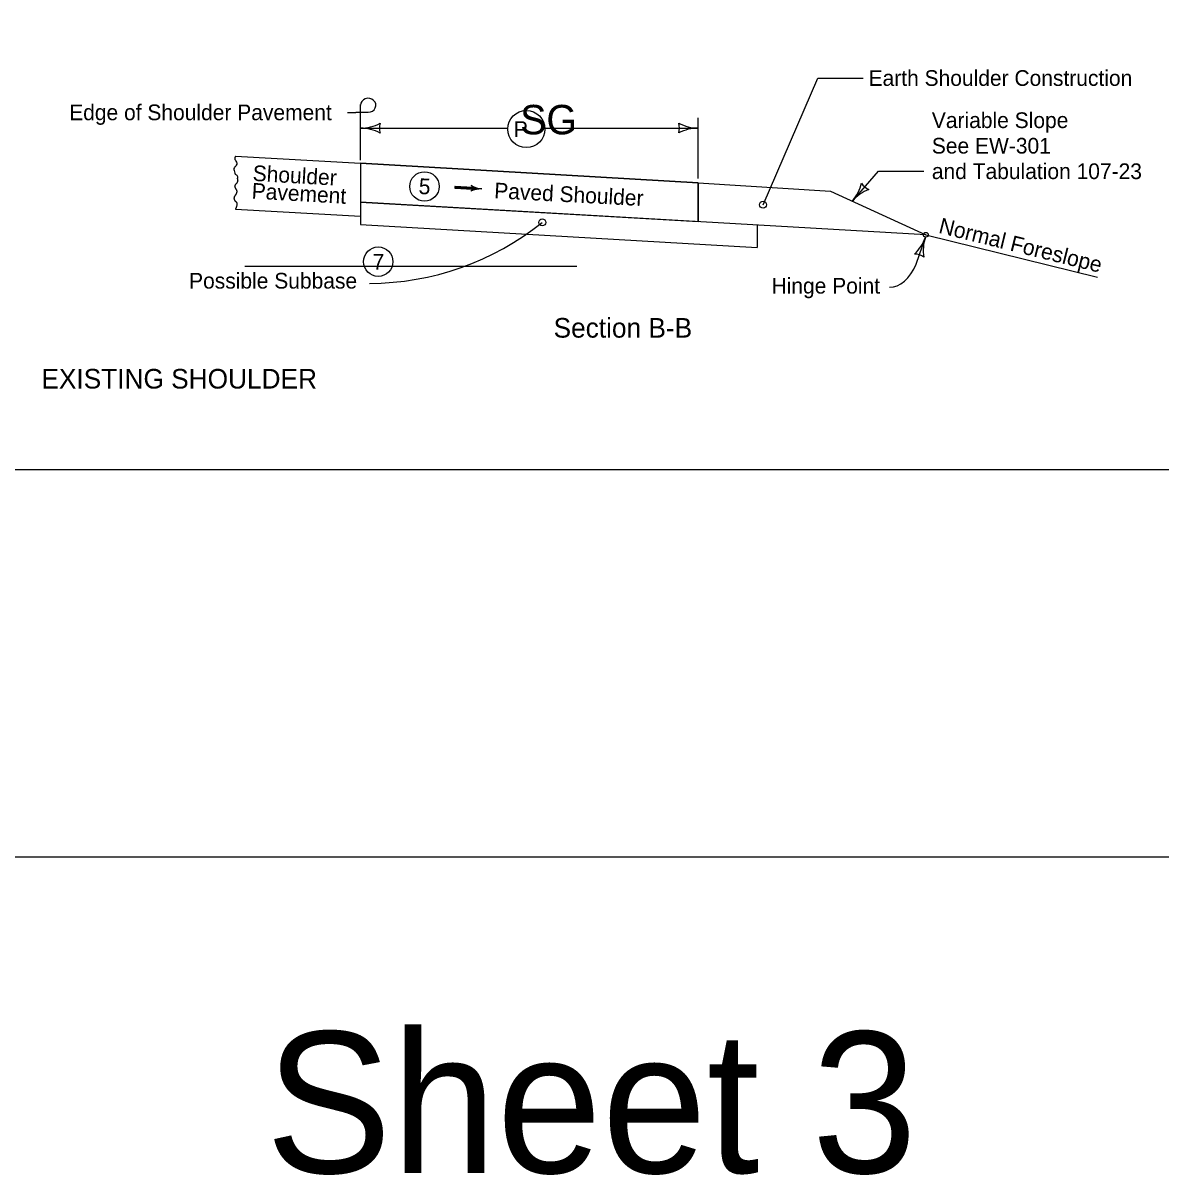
# Model space of a CAD drawing. Extents: x 9538 to 81668, y 7600 to 11751.
# Drawn here: x 18260 to 19420, y 7600 to 8774 of the extents above; entities that cross this region are included whole.
import ezdxf

# ---------------------------------------------------------------- set-up
doc = ezdxf.new("R2010")
doc.units = 0
for name, color, linetype in [('Default', 7, 'Continuous'), ('DsnShtMinorGrid13', 7, 'Continuous'), ('DsnShtMinorGrid14', 7, 'Continuous'), ('dsnStdDimension', 7, 'Continuous'), ('dsnStdNote', 7, 'Continuous'), ('dsnStdShading', 7, 'Continuous'), ('dsnStdTable', 7, 'Continuous'), ('Level 13', 7, 'Continuous')]:
    doc.layers.add(name, color=color, linetype=linetype)

msp = doc.modelspace()

# ---------------------------------------------------------------- linework, layer by layer
at = {"layer": 'Default'}
msp.add_lwpolyline([(17332.5, 9944), (20467.5, 9944), (20467.5, 7924), (17332.5, 7924)], close=True, dxfattribs=at)
at = {"layer": 'DsnShtMinorGrid13'}
for centre in [(18669.2, 8607.5), (18622.1, 8530.8)]:
    msp.add_circle(centre, 15, dxfattribs=at)
at = {"layer": 'DsnShtMinorGrid14'}
for centre in [(19014.3, 8588.9), (18789.3, 8570.8)]:
    msp.add_circle(centre, 3.54, dxfattribs=at)
at = {"layer": 'dsnStdDimension'}
for p, q in [((18948.3, 8615.7), (18948.3, 8677.4)), ((18604, 8666.9), (18754, 8666.9)), ((18791.9, 8667), (18948.3, 8667))]:
    msp.add_line(p, q, dxfattribs=at)
msp.add_circle((18773, 8666), 18.9, dxfattribs=at)
for centre, radius, start, end in [((18604, 8709.4), 42.5, 270, 298.0725), ((18604, 8624.4), 42.5, 61.9275, 90), ((18639.7, 8666.9), 16.4, 162.2666, 197.7334), ((18912.7, 8667), 16.4, 342.2666, 17.7333), ((18948.3, 8709.5), 42.5, 241.9275, 270), ((18948.3, 8624.5), 42.5, 90, 118.0725), ((18612.6, 8790.7), 282, 270.132, 308.7946)]:
    msp.add_arc(centre, radius, start, end, dxfattribs=at)
at = {"layer": 'dsnStdNote'}
for p, q in [((19014.3, 8588.9), (19070, 8718)), ((19070, 8718), (19116.3, 8718)), ((18604, 8670.2), (18604, 8691)), ((18590.7, 8683), (18599.4, 8683)), ((18611.9, 8683), (18599.4, 8683)), ((18604, 8634.2), (18604, 8670.2)), ((19105.3, 8592.6), (19131.9, 8623)), ((19131.9, 8623), (19178.2, 8623)), ((18718.3, 8605.6), (18700.1, 8606.6)), ((18718.3, 8606.6), (18718.3, 8606.6)), ((18718.2, 8604.7), (18718.2, 8604.7)), ((19170.4, 8528.4), (19179.8, 8555.9))]:
    msp.add_line(p, q, dxfattribs=at)
for points in [[(18718.3, 8606.5), (18700.2, 8607.6), (18700, 8605.7), (18718.2, 8604.7), (18718.3, 8606.3), (18700.4, 8607.4), (18700.3, 8605.9), (18717.8, 8604.9), (18718, 8606), (18700.6, 8607.1), (18700.6, 8606.1), (18717.6, 8605.1), (18717.7, 8605.8), (18700.8, 8606.9), (18700.8, 8606.3), (18717.4, 8605.4)], [(18717.9, 8607.8), (18718.6, 8606.6), (18718.6, 8605), (18717.9, 8603.6), (18720.6, 8604.4), (18723.8, 8605.1), (18724.7, 8605.2), (18722.5, 8605.8), (18719.2, 8607), (18718.3, 8607.5), (18718.4, 8604), (18723.4, 8605.2), (18718.7, 8606.8), (18718.7, 8604.4), (18722.1, 8605.3), (18719.1, 8606.2), (18718.9, 8604.8), (18721.1, 8605.3), (18719.5, 8605.8), (18719.3, 8605.2), (18720.1, 8605.3)]]:
    msp.add_lwpolyline(points, dxfattribs=at)
for centre, radius, start, end in [((19073.3, 8620.6), 42.5, 318.8454, 346.9178), ((19128.7, 8619.4), 16.4, 211.112, 246.5787), ((19137.3, 8564.6), 42.5, 110.7729, 138.8454), ((19139.7, 8569.7), 42.5, 312.9788, 341.0513), ((19220, 8542.1), 42.5, 161.0513, 189.1238), ((19168.3, 8522.2), 16.4, 53.3179, 88.7846)]:
    msp.add_arc(centre, radius, start, end, dxfattribs=at)
for centre, major_axis, ratio, start_param, end_param in [((18611.9, 8690.2), (-7.81, 0), 0.913811, 1.570796, 6.283185), ((18714.5, 8605.8), (3.88, 0), 0.913811, 5.202895, 7.237436), ((18729.6, 8625.2), (-22.2, 0), 0.913811, 0.954258, 1.478381), ((18726.8, 8584.8), (22.2, 0), 0.913811, 1.537172, 2.061295), ((19143.3, 8566.2), (0, 61.5), 0.559383, 3.141593, 4.048985)]:
    msp.add_ellipse(centre, major_axis=major_axis, ratio=ratio, start_param=start_param, end_param=end_param, dxfattribs=at)
at = {"layer": 'dsnStdShading'}
msp.add_line((17347.5, 8319), (20443.2, 8319), dxfattribs=at)
at = {"layer": 'dsnStdTable'}
for p, q in [((18476.6, 8638.5), (18604, 8631.1)), ((18604, 8631.1), (18604, 8577.1)), ((18604, 8631.1), (18948.3, 8611.1)), ((18948.3, 8611.1), (18604, 8631.1)), ((18604, 8631.1), (18604, 8591.5)), ((18947.9, 8611.3), (18947.9, 8611.3)), ((18948.3, 8611.2), (19083.1, 8602.8)), ((18948.3, 8571.7), (18948.3, 8611.1)), ((18948.3, 8611.1), (18948.3, 8571.7)), ((19083.1, 8602.8), (19180.1, 8558.3)), ((18476.6, 8584.5), (18604, 8577.1)), ((19180.1, 8558.3), (18604, 8591.5)), ((18604, 8591.5), (18948.3, 8571.7)), ((18604, 8577.1), (18604, 8568.7)), ((18604, 8568.7), (19008.3, 8545.4)), ((19008.3, 8568.2), (19008.3, 8545.4)), ((19180.1, 8558.3), (19355.1, 8515)), ((18486, 8526.2), (18824.5, 8526.2))]:
    msp.add_line(p, q, dxfattribs=at)
msp.add_circle((18669.2, 8607.5), 15, dxfattribs=at)
msp.add_ellipse((19180.1, 8558.3), major_axis=(2.58, 0), ratio=0.913811, dxfattribs=at)
for points in [[(18476.6, 8638.5), (18476.1, 8634.9), (18477.1, 8633.4), (18478, 8631.1), (18477.4, 8629.1), (18475.5, 8626.7), (18474.9, 8624.8), (18475.5, 8622.5), (18476.3, 8620.1), (18477.4, 8619.4), (18478.8, 8616.9), (18478.7, 8616)], [(18476.8, 8598.9), (18477, 8599.2), (18477.2, 8599.4), (18477.5, 8600), (18477.8, 8600.6), (18477.9, 8600.9), (18478, 8601.2), (18478.2, 8601.8), (18478.2, 8602.4), (18478.2, 8603), (18478.1, 8603.3), (18478.1, 8603.4), (18478, 8603.6), (18477.8, 8603.9), (18477.5, 8604.3), (18477.2, 8604.7), (18477, 8605.1), (18476.9, 8605.3), (18476.7, 8605.6), (18476.5, 8606.2), (18476.3, 8606.8), (18476.2, 8607.1), (18476.1, 8607.4), (18476.1, 8607.5), (18476.1, 8607.6), (18476.3, 8608.4), (18476.5, 8608.9), (18476.7, 8609.4), (18477.2, 8610.1), (18477.7, 8610.6), (18478.2, 8611.1), (18478.4, 8611.4), (18478.6, 8611.8), (18478.9, 8612.3), (18479, 8612.7), (18479.1, 8613.2), (18479.1, 8613.5), (18479.2, 8613.6), (18479.2, 8613.7), (18479.1, 8614.2), (18479, 8614.7), (18478.9, 8614.8), (18478.9, 8615), (18478.8, 8615.1), (18478.8, 8615.2), (18478.7, 8616)], [(18476.8, 8598.9), (18476.6, 8598.7), (18476.3, 8598.4), (18476.1, 8598.2), (18475.9, 8597.9), (18475.8, 8597.6), (18475.6, 8597.4), (18475.4, 8596.8), (18475.3, 8596.5), (18475.2, 8596.2), (18475.1, 8595.9), (18475.1, 8595.8), (18475, 8595.6), (18475.1, 8595.1), (18475.2, 8594.6), (18475.4, 8594.1), (18475.6, 8593.6), (18476.1, 8592.9), (18476.6, 8592.4), (18477.1, 8591.8), (18477.4, 8591.5), (18477.6, 8591.2), (18478, 8590.2), (18478.1, 8589.8), (18478.1, 8589.3), (18478, 8589), (18478, 8588.7), (18477.9, 8588.4), (18477.9, 8588.1), (18477.6, 8587), (18477.4, 8586.4), (18477.2, 8585.8), (18477, 8585.2), (18476.8, 8584.9), (18476.7, 8584.6), (18476.6, 8584.5)]]:
    msp.add_spline(points, degree=3, dxfattribs=at)

# ---------------------------------------------------------------- texts
at = {"layer": 'DsnShtMinorGrid13'}
msp.add_text('5', height=16, rotation=356.6997, dxfattribs=at).set_placement((18663, 8599.9))
msp.add_text('7', height=16, dxfattribs=at).set_placement((18616.4, 8522.8))
at = {"layer": 'dsnStdDimension'}
for s, height, p in [('SG', 30, (18766.7, 8660.6)), ('P', 16, (18760.2, 8658))]:
    msp.add_text(s, height=height, dxfattribs=at).set_placement(p)
at = {"layer": 'dsnStdNote'}
for s, height, p in [('Earth Shoulder Construction', 16, (19121.8, 8710)), ('Edge of Shoulder Pavement', 16, (18307.1, 8675)), ('Variable Slope', 16, (19186.3, 8667)), ('See EW-301', 16, (19186.3, 8641)), ('and Tabulation 107-23', 16, (19186.3, 8615)), ('Possible Subbase', 16, (18429.3, 8503.4)), ('Hinge Point', 16, (19022.9, 8498.3)), ('Section B-B', 20, (18800.8, 8453.4)), ('EXISTING SHOULDER', 20, (18278.8, 8401.5))]:
    msp.add_text(s, height=height, dxfattribs=at).set_placement(p)
for s, rotation, p in [('Shoulder', 356.7346, (18493.8, 8613.2)), ('Pavement', 356.7346, (18492.8, 8595.2)), ('Paved Shoulder ', 356.983, (18740, 8595.5)), ('Normal Foreslope', 346.0988, (19192.4, 8560.3))]:
    msp.add_text(s, height=16, rotation=rotation, dxfattribs=at).set_placement(p)
at = {"layer": 'Level 13'}
msp.add_text('Sheet 3', height=144, dxfattribs=at).set_placement((18507.3, 7602))

doc.saveas('drawing.dxf')
